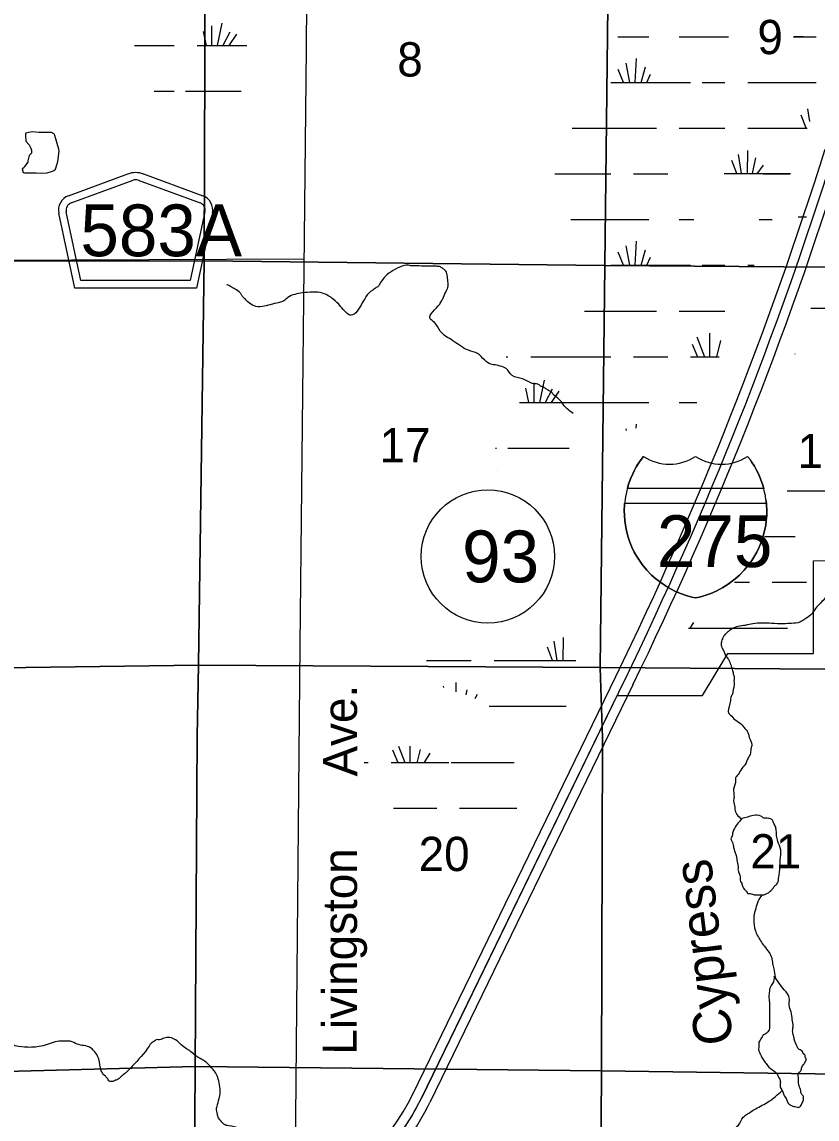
# Model space of a CAD drawing. Extents: x 380424 to 701066, y 1117407 to 1412949.
# Drawn here: x 513753 to 524199, y 1373482 to 1387886 of the extents above; entities that cross this region are included whole.
import ezdxf

# ---------------------------------------------------------------- set-up
doc = ezdxf.new("R2010")
doc.units = 0
for name, color, linetype in [('Cities Incorporated Area', 7, 'Continuous'), ('County Routes Highway Center Lines', 7, 'Continuous'), ('Interstate Divided Highway Outline and Fill', 7, 'Continuous'), ('Interstate Highway Center Lines', 7, 'Continuous'), ('Lakes and Ponds', 7, 'Continuous'), ('Local Roads Paved', 7, 'Continuous'), ('Local Roads Related Text', 7, 'Continuous'), ('Narrow River Creek and Branch and Slough', 7, 'Continuous'), ('Narrow River Creek and Branch and Slough Text', 7, 'Continuous'), ('Roadshields County Roads', 7, 'Continuous'), ('Roadshields Interstates', 7, 'Continuous'), ('Section Lines', 7, 'Continuous'), ('Section Numbers', 7, 'Continuous'), ('Swamps', 7, 'Continuous')]:
    doc.layers.add(name, color=color, linetype=linetype)

msp = doc.modelspace()

# ---------------------------------------------------------------- linework, layer by layer
at = {"layer": 'Cities Incorporated Area'}
msp.add_lwpolyline([(519001, 1373755), (521574, 1379045), (522696, 1379043), (523025, 1379596), (524154, 1379596), (524154, 1380812), (526832, 1380817), (526844, 1382202), (528060, 1382202), (528061, 1383504), (529275, 1383505), (529270, 1384771), (530889, 1384771), (530889, 1385981), (529270, 1385981), (529290, 1387758), (530767, 1387752), (529457, 1389968)], dxfattribs=at)
msp.add_arc((516112, 1375160), 3212, 319.5366, 334.0599, dxfattribs=at)
at = {"layer": 'County Routes Highway Center Lines'}
msp.add_lwpolyline([(517457, 1384773), (507279, 1384726)], dxfattribs=at)
at = {"layer": 'Interstate Divided Highway Outline and Fill'}
for p, q in [((518888, 1373809), (521555, 1379291)), ((521780, 1379182), (519113, 1373700))]:
    msp.add_line(p, q, dxfattribs=at)
for centre, radius, start, end in [((476737, 1401092), 49839, 334.0597, 342.6352), ((476737, 1401092), 50089, 334.0597, 342.6352), ((516112, 1375160), 3087, 295.0995, 334.0599), ((516112, 1375160), 3337, 295.0995, 334.0599)]:
    msp.add_arc(centre, radius, start, end, dxfattribs=at)
at = {"layer": 'Interstate Highway Center Lines'}
msp.add_line((521667, 1379236), (519001, 1373755), dxfattribs=at)
for centre, radius, start, end in [((476737, 1401092), 49964, 334.0597, 342.6352), ((516112, 1375160), 3212, 295.0995, 334.0599)]:
    msp.add_arc(centre, radius, start, end, dxfattribs=at)
at = {"layer": 'Lakes and Ponds'}
msp.add_lwpolyline([(513831, 1386047), (513789, 1385989), (513778, 1385973), (513757, 1385958), (513768, 1385910), (513789, 1385905), (513942, 1385905), (514011, 1385900), (514085, 1385905), (514153, 1385926), (514174, 1385934), (514196, 1385952), (514211, 1386010), (514227, 1386053), (514244, 1386191), (514238, 1386216), (514185, 1386396), (514180, 1386412), (514143, 1386433), (514058, 1386433), (513974, 1386433), (513889, 1386443), (513842, 1386433), (513805, 1386428), (513800, 1386412), (513800, 1386391), (513805, 1386322), (513847, 1386274), (513868, 1386227), (513879, 1386201), (513879, 1386164), (513847, 1386132), (513831, 1386063)], close=True, dxfattribs=at)
for points in [[(523209, 1377426), (523362, 1377466), (523462, 1377460), (523504, 1377434), (523525, 1377434), (523562, 1377429), (523605, 1377413), (523626, 1377376), (523652, 1377323), (523663, 1377270), (523668, 1377202), (523684, 1377128), (523721, 1377017), (523716, 1376885), (523710, 1376784), (523705, 1376716), (523694, 1376642), (523668, 1376563), (523647, 1376547), (523620, 1376510), (523594, 1376483), (523547, 1376446), (523510, 1376431), (523494, 1376425), (523462, 1376425), (523409, 1376425), (523362, 1376431), (523335, 1376441), (523282, 1376452), (523277, 1376462), (523272, 1376473), (523240, 1376499), (523224, 1376531), (523209, 1376579), (523209, 1376584), (523203, 1376589), (523187, 1376658), (523161, 1376748), (523161, 1376800), (523150, 1376858), (523135, 1376943), (523119, 1376990), (523103, 1377049), (523087, 1377112), (523071, 1377175), (523077, 1377181), (523087, 1377223), (523103, 1377276), (523209, 1377426)], [(523636, 1375359), (523768, 1375179), (523837, 1375058), (523832, 1374978), (523858, 1374889), (523874, 1374788), (523885, 1374704), (523879, 1374656), (523885, 1374593), (523895, 1374561), (523906, 1374503), (523916, 1374482), (523964, 1374397), (524011, 1374361), (524017, 1374345), (524038, 1374324), (524043, 1374308), (524043, 1374297), (524054, 1374276), (524048, 1374239), (524022, 1374197), (523995, 1374149), (523990, 1374123), (523958, 1374091), (523953, 1374028), (523958, 1373933), (523980, 1373869), (524001, 1373806), (524022, 1373769), (524017, 1373753), (524022, 1373743), (524017, 1373722), (523995, 1373674), (523964, 1373637), (523943, 1373637), (523906, 1373648), (523895, 1373648), (523863, 1373658), (523821, 1373690), (523805, 1373716), (523784, 1373764), (523779, 1373769), (523763, 1373801), (523742, 1373854), (523716, 1373906), (523716, 1373954), (523710, 1374007), (523694, 1374033), (523673, 1374075), (523636, 1374112), (523547, 1374186), (523510, 1374239), (523473, 1374292), (523457, 1374329), (523441, 1374361), (523430, 1374403), (523436, 1374440), (523436, 1374493), (523451, 1374519), (523488, 1374577), (523515, 1374598), (523541, 1374614), (523573, 1374672), (523573, 1374725), (523573, 1374751), (523573, 1374846), (523573, 1374952), (523573, 1375010), (523568, 1375058), (523568, 1375121), (523573, 1375163), (523594, 1375237), (523615, 1375264), (523636, 1375359)]]:
    msp.add_spline(points, degree=3, dxfattribs=at)
at = {"layer": 'Local Roads Paved'}
msp.add_lwpolyline([(518204, 1395197), (518154, 1394842), (518069, 1394603), (517816, 1394145), (517668, 1393892), (517563, 1393660), (517563, 1393125), (517528, 1392688), (517514, 1391246), (517486, 1387536), (517404, 1379706), (517289, 1367298), (517256, 1362220)], dxfattribs=at)
at = {"layer": 'Narrow River Creek and Branch and Slough'}
for points in [[(518757, 1384686), (518524, 1384542), (518482, 1384489), (518450, 1384442), (518429, 1384410), (518409, 1384399), (518361, 1384363), (518350, 1384357), (518290, 1384302), (518224, 1384197), (518077, 1384035), (517938, 1384152), (517842, 1384248), (517703, 1384324), (517439, 1384329)], [(520995, 1382745), (520878, 1382847), (520840, 1382900), (520789, 1382949), (520741, 1382988), (520716, 1383019), (520679, 1383044), (520637, 1383070), (520601, 1383094), (520564, 1383106), (520547, 1383122), (520478, 1383137), (520330, 1383201), (520193, 1383243), (520116, 1383335), (520080, 1383352), (519987, 1383380), (519913, 1383393), (519833, 1383446), (519739, 1383532), (519619, 1383576), (519414, 1383701), (519248, 1383828), (519173, 1383942), (519117, 1383989), (519242, 1384183), (519256, 1384206), (519270, 1384231), (519281, 1384250), (519320, 1384339), (519342, 1384383), (519342, 1384542), (519322, 1384616), (519286, 1384647), (519253, 1384669), (519198, 1384678), (519156, 1384678), (519098, 1384678), (518973, 1384683), (518929, 1384686), (518904, 1384683), (518876, 1384683), (518848, 1384689), (518757, 1384686)], [(517439, 1384329), (517246, 1384268), (517193, 1384225), (517072, 1384188), (517014, 1384173), (516803, 1384157), (516723, 1384210), (516686, 1384249), (516650, 1384283), (516644, 1384294), (516623, 1384326), (516554, 1384379), (516507, 1384405), (516482, 1384423), (516446, 1384436)], [(526441, 1383988), (526314, 1383306), (526198, 1383069), (526198, 1382979), (526187, 1382916), (526192, 1382831), (526203, 1382731), (526245, 1382594), (526287, 1382472), (526335, 1382319), (526393, 1382203), (526446, 1382050), (526462, 1381881), (526472, 1381780), (526462, 1381669), (526435, 1381611), (526340, 1381500), (526250, 1381374), (526103, 1381247), (525944, 1381036), (525833, 1380925), (525738, 1380861), (525696, 1380803), (525617, 1380708), (525569, 1380587), (525527, 1380529), (525474, 1380492), (525411, 1380460), (525342, 1380423), (525273, 1380407), (525163, 1380402), (525025, 1380434), (524946, 1380471), (524735, 1380523), (524682, 1380518), (524561, 1380523), (524487, 1380486), (524429, 1380444), (524365, 1380397), (524291, 1380307), (524180, 1380185), (524117, 1380101), (524027, 1380038), (523974, 1380006), (523863, 1379990), (523758, 1379985), (523599, 1379990), (523356, 1379985), (523256, 1379964), (523077, 1379916), (523024, 1379874), (522992, 1379847), (522976, 1379826), (522955, 1379789), (522945, 1379758), (522939, 1379705), (522966, 1379641), (522987, 1379589), (523034, 1379515), (523087, 1379372), (523103, 1379314), (523108, 1379293), (523108, 1379245), (523108, 1379214), (523108, 1379171), (523098, 1379124), (523087, 1379066), (523066, 1379018), (523061, 1378976), (523045, 1378897), (523034, 1378855), (523040, 1378807), (523061, 1378786), (523124, 1378723), (523209, 1378664), (523240, 1378622), (523282, 1378575), (523309, 1378490), (523341, 1378400), (523330, 1378342), (523319, 1378268), (523288, 1378210), (523267, 1378158), (523209, 1378084), (523161, 1378004), (523129, 1377957), (523129, 1377930), (523103, 1377814), (523108, 1377714), (523103, 1377656), (523119, 1377577), (523119, 1377550), (523204, 1377419)], [(515847, 1374456), (515772, 1374523), (515620, 1374545), (515562, 1374524), (515509, 1374519), (515498, 1374508), (515472, 1374493), (515445, 1374471), (515424, 1374440), (515202, 1374176), (515113, 1374086), (515060, 1374044), (515018, 1374007), (514981, 1373991), (514933, 1373975), (514896, 1373986), (514880, 1374012), (514849, 1374044), (514801, 1374102), (514785, 1374155), (514748, 1374308), (514695, 1374382), (514653, 1374419), (514479, 1374466), (514389, 1374503), (514326, 1374503), (514241, 1374503), (514030, 1374445), (513829, 1374424), (513666, 1374445), (513507, 1374493), (513349, 1374529), (513185, 1374545), (512953, 1374561), (512736, 1374572), (512525, 1374593), (512440, 1374625), (512372, 1374640), (512361, 1374640), (512298, 1374646), (512271, 1374635), (512208, 1374646), (512161, 1374662), (512081, 1374704), (512029, 1374746), (512002, 1374831), (511891, 1375163), (511865, 1375390), (511854, 1375506), (511865, 1375675), (511881, 1375760), (511891, 1375844), (511897, 1375929), (511891, 1375998), (511881, 1376040), (511833, 1376135), (511801, 1376193), (511733, 1376251), (511706, 1376267), (511622, 1376304), (511559, 1376325), (511395, 1376330), (511337, 1376336), (511279, 1376367), (511231, 1376394), (511210, 1376415), (511168, 1376526), (511147, 1376610), (511126, 1376732), (511115, 1376938), (511099, 1377154), (511046, 1377291), (511004, 1377418), (510957, 1377497), (510930, 1377529), (510909, 1377550), (510856, 1377592), (510851, 1377614), (510851, 1377651), (510830, 1377952)], [(523473, 1376425), (523425, 1376346), (523393, 1376246), (523378, 1376193), (523367, 1376103), (523388, 1375955), (523457, 1375823), (523504, 1375755), (523568, 1375670), (523599, 1375607), (523615, 1375522), (523631, 1375454), (523647, 1375344)], [(517200, 1373250), (516871, 1373294), (516613, 1373362), (516470, 1373394), (516438, 1373399), (516380, 1373442), (516343, 1373484), (516333, 1373500), (516322, 1373542), (516311, 1373626), (516317, 1373648), (516343, 1373753), (516354, 1373790), (516354, 1373906), (516333, 1374007), (516301, 1374086), (516264, 1374133), (516179, 1374223), (516116, 1374265), (516037, 1374313), (515973, 1374366), (515915, 1374403), (515847, 1374456)], [(523589, 1368419), (523557, 1368462), (523541, 1368499), (523494, 1368573), (523478, 1368620), (523462, 1368652), (523451, 1368694), (523451, 1368747), (523446, 1368784), (523462, 1368837), (523494, 1368900), (523520, 1368937), (523552, 1369043), (523562, 1369101), (523568, 1369169), (523552, 1369212), (523531, 1369238), (523520, 1369264), (523499, 1369307), (523467, 1369365), (523362, 1369528), (523309, 1369597), (523288, 1369634), (523261, 1369703), (523235, 1369777), (523219, 1369829), (523214, 1369866), (523198, 1369967), (523193, 1370004), (523209, 1370041), (523145, 1370157), (523140, 1370173), (523108, 1370199), (523066, 1370241), (523003, 1370284), (522944, 1370326), (522876, 1370373), (522834, 1370395), (522786, 1370458), (522754, 1370505), (522739, 1370548), (522733, 1370611), (522733, 1370643), (522733, 1370680), (522712, 1370711), (522675, 1370743), (522649, 1370759), (522622, 1370764), (522580, 1370769), (522527, 1370780), (522469, 1370780), (522416, 1370775), (522406, 1370769), (522342, 1370791), (522316, 1370796), (522295, 1370806), (522263, 1370849), (522263, 1370933), (522263, 1370949), (522279, 1371012), (522284, 1371039), (522305, 1371081), (522358, 1371129), (522443, 1371160), (522511, 1371202), (522548, 1371245), (522622, 1371340), (522665, 1371414), (522686, 1371493), (522717, 1371588), (522765, 1371683), (522797, 1371831), (522786, 1371974), (522812, 1372084), (522839, 1372248), (522849, 1372354), (522855, 1372417), (522860, 1372486), (522881, 1372560), (522886, 1372607), (522876, 1372634), (522865, 1372708), (522855, 1372766), (522860, 1372803), (522923, 1372935), (522966, 1373030), (523040, 1373193), (523103, 1373325), (523124, 1373362), (523177, 1373415), (523209, 1373479), (523230, 1373505), (523272, 1373542), (523330, 1373579), (523393, 1373616), (523562, 1373711), (523741, 1373856)]]:
    msp.add_spline(points, degree=3, dxfattribs=at)
at = {"layer": 'Roadshields County Roads'}
for p, q in [((514364, 1385604), (515144, 1385890)), ((515351, 1385890), (516129, 1385604)), ((514399, 1385510), (515213, 1385809)), ((515282, 1385809), (516094, 1385510)), ((514448, 1384392), (514238, 1385374)), ((514529, 1384492), (514336, 1385395)), ((516158, 1385395), (515964, 1384492)), ((516255, 1385374), (516045, 1384392)), ((516045, 1384392), (514448, 1384392)), ((515964, 1384492), (514529, 1384492))]:
    msp.add_line(p, q, dxfattribs=at)
for centre, radius, start, end in [((515247, 1385608), 300, 69.8264, 110.1725), ((515247, 1385715), 100, 69.8265, 110.1725), ((514433, 1385416), 200, 110.1725, 192.0994), ((516060, 1385416), 200, 347.8996, 69.8265), ((514433, 1385416), 100, 110.1725, 192.0994), ((516060, 1385416), 100, 347.8996, 69.8265)]:
    msp.add_arc(centre, radius, start, end, dxfattribs=at)
at = {"layer": 'Roadshields Interstates'}
for p, q in [((521707, 1381762), (521708, 1381768)), ((523498, 1381762), (521707, 1381762)), ((523534, 1381562), (521671, 1381562)), ((523528, 1381612), (523534, 1381562))]:
    msp.add_line(p, q, dxfattribs=at)
for points in [[(521918, 1382183), (521887, 1382141), (521867, 1382112), (521828, 1382052), (521800, 1382001), (521777, 1381954), (521747, 1381886), (521719, 1381806), (521699, 1381735), (521695, 1381712)], [(521708, 1381768), (521707, 1381762), (521719, 1381806), (521747, 1381886), (521777, 1381954), (521800, 1382001), (521828, 1382052), (521867, 1382112), (521887, 1382141), (521918, 1382183)], [(523510, 1381712), (523506, 1381735), (523486, 1381806), (523458, 1381886), (523428, 1381954), (523405, 1382001), (523377, 1382052), (523338, 1382112), (523318, 1382141), (523287, 1382183)], [(523287, 1382183), (523318, 1382141), (523338, 1382112), (523377, 1382052), (523405, 1382001), (523428, 1381954), (523458, 1381886), (523486, 1381806), (523498, 1381762)], [(521684, 1381662), (521677, 1381612)], [(521695, 1381712), (521685, 1381667), (521684, 1381662)], [(523521, 1381662), (523520, 1381667), (523510, 1381712)], [(523528, 1381612), (523521, 1381662)], [(521677, 1381612), (521674, 1381594), (521670, 1381550), (521667, 1381473), (521668, 1381408), (521673, 1381341), (521681, 1381279), (521696, 1381203), (521718, 1381120), (521740, 1381057), (521767, 1380991), (521798, 1380926), (521823, 1380881), (521865, 1380814), (521901, 1380763), (521962, 1380689), (522025, 1380624), (522082, 1380573), (522176, 1380503), (522245, 1380459), (522330, 1380415), (522403, 1380383), (522492, 1380352), (522552, 1380336), (522603, 1380325)], [(521671, 1381562), (521672, 1381563), (521670, 1381550), (521667, 1381473), (521668, 1381408), (521673, 1381341), (521681, 1381279), (521696, 1381203), (521718, 1381120), (521740, 1381057), (521767, 1380991), (521798, 1380926), (521823, 1380881), (521865, 1380814), (521901, 1380763), (521962, 1380689), (522025, 1380624), (522082, 1380573), (522176, 1380503), (522245, 1380459), (522330, 1380415), (522403, 1380383), (522492, 1380352), (522552, 1380336), (522603, 1380325)], [(522603, 1380325), (522552, 1380336), (522492, 1380352), (522403, 1380383), (522330, 1380415), (522245, 1380459), (522176, 1380503), (522082, 1380573), (522025, 1380624), (521962, 1380689), (521901, 1380763), (521865, 1380814), (521823, 1380881), (521798, 1380926), (521767, 1380991), (521740, 1381057), (521718, 1381120), (521696, 1381203), (521681, 1381279), (521673, 1381341), (521668, 1381408), (521667, 1381473), (521670, 1381550), (521671, 1381562)], [(522603, 1380325), (522653, 1380336), (522713, 1380352), (522802, 1380383), (522875, 1380415), (522960, 1380459), (523029, 1380503), (523123, 1380573), (523180, 1380624), (523243, 1380689), (523304, 1380763), (523340, 1380814), (523382, 1380881), (523407, 1380926), (523438, 1380991), (523466, 1381057), (523487, 1381120), (523509, 1381203), (523524, 1381279), (523532, 1381341), (523537, 1381408), (523538, 1381473), (523535, 1381550), (523531, 1381594), (523528, 1381612)], [(522603, 1380325), (522653, 1380336), (522713, 1380352), (522802, 1380383), (522875, 1380415), (522960, 1380459), (523029, 1380503), (523123, 1380573), (523180, 1380624), (523243, 1380689), (523304, 1380763), (523340, 1380814), (523382, 1380881), (523407, 1380926), (523438, 1380991), (523466, 1381057), (523487, 1381120), (523509, 1381203), (523524, 1381279), (523532, 1381341), (523537, 1381408), (523538, 1381473), (523535, 1381550), (523531, 1381594), (523528, 1381612)], [(523534, 1381562), (523535, 1381550), (523538, 1381473), (523537, 1381408), (523532, 1381341), (523524, 1381279), (523509, 1381203), (523487, 1381120), (523466, 1381057), (523438, 1380991), (523407, 1380926), (523382, 1380881), (523340, 1380814), (523304, 1380763), (523243, 1380689), (523180, 1380624), (523123, 1380573), (523029, 1380503), (522960, 1380459), (522875, 1380415), (522802, 1380383), (522713, 1380352), (522653, 1380336), (522603, 1380325)]]:
    msp.add_lwpolyline(points, dxfattribs=at)
msp.add_circle((519874, 1380869), 875, dxfattribs=at)
for centre, radius, start, end in [((522812, 1381470), 1143, 141.4155, 165.1746), ((522261, 1382698), 619, 236.3685, 303.409), ((522261, 1382698), 619, 236.3685, 303.409), ((522261, 1382698), 619, 236.3685, 303.409), ((522944, 1382703), 623, 236.8281, 303.3923), ((522944, 1382703), 623, 236.8281, 303.3923), ((522944, 1382703), 623, 236.8281, 303.3923)]:
    msp.add_arc(centre, radius, start, end, dxfattribs=at)
at = {"layer": 'Section Lines'}
for points in [[(516166, 1390051), (516147, 1384751), (510484, 1384742), (510477, 1384742), (510408, 1390118), (516156, 1390051)], [(521471, 1389984), (521413, 1384687), (521406, 1384687), (516147, 1384751), (516166, 1390051)], [(526752, 1389920), (526712, 1384648), (526707, 1384648), (521413, 1384687), (521471, 1389984)], [(516147, 1384751), (516074, 1379448), (516074, 1379440), (510560, 1379365), (510479, 1384736), (510477, 1384742), (510484, 1384742)], [(521413, 1384687), (521351, 1379411), (516074, 1379440), (516074, 1379448), (516147, 1384751), (521406, 1384687)], [(526712, 1384648), (526712, 1384642), (526663, 1379370), (521351, 1379411), (521413, 1384687), (526707, 1384648)], [(516074, 1379440), (516056, 1378507), (516030, 1374171), (510557, 1374026), (510558, 1374169), (510562, 1378527), (510560, 1379365)], [(521351, 1379411), (521351, 1379405), (521382, 1378488), (521365, 1374116), (516038, 1374171), (516030, 1374171), (516056, 1378507), (516074, 1379440)], [(526663, 1379370), (526663, 1379363), (526672, 1378473), (526670, 1374041), (521365, 1374116), (521382, 1378488), (521351, 1379405), (521351, 1379411)], [(516030, 1374171), (516030, 1374159), (515992, 1368894), (510634, 1368757), (510631, 1368928), (510557, 1374026)], [(521365, 1374116), (521334, 1368815), (515992, 1368894), (516030, 1374159), (516030, 1374171), (516038, 1374171)], [(526670, 1374041), (526628, 1368762), (526620, 1368762), (521346, 1368815), (521334, 1368815), (521365, 1374116)]]:
    msp.add_lwpolyline(points, close=True, dxfattribs=at)
at = {"layer": 'Swamps'}
for p, q in [((516378, 1387871), (516319, 1387576)), ((516136, 1387762), (516173, 1387576)), ((516245, 1387835), (516245, 1387576)), ((516486, 1387750), (516392, 1387575)), ((516571, 1387726), (516472, 1387577)), ((515454, 1387576), (515754, 1387576)), ((522388, 1387691), (523034, 1387691)), ((523888, 1387691), (524188, 1387691)), ((524018, 1387691), (523888, 1387691)), ((521739, 1387091), (521693, 1387345)), ((521810, 1387091), (521827, 1387407)), ((521887, 1387091), (521945, 1387295)), ((521654, 1387091), (521588, 1387263)), ((521963, 1387091), (522012, 1387199)), ((521488, 1387091), (522538, 1387091)), ((522688, 1387091), (522988, 1387091)), ((523288, 1387091), (523888, 1387091)), ((523888, 1387091), (524188, 1387091)), ((524054, 1386492), (523988, 1386664)), ((522388, 1386491), (522988, 1386491)), ((523288, 1386491), (523888, 1386491)), ((523206, 1385895), (523167, 1386148)), ((523284, 1385895), (523290, 1386199)), ((523144, 1385896), (523078, 1386069)), ((523351, 1385895), (523394, 1386101)), ((523414, 1385894), (523497, 1386008)), ((521788, 1385891), (522238, 1385891)), ((522978, 1385895), (523850, 1385895)), ((523492, 1385891), (523840, 1385891)), ((522388, 1385291), (522579, 1385291)), ((521810, 1384691), (521827, 1385007)), ((521654, 1384691), (521588, 1384863)), ((521739, 1384691), (521693, 1384945)), ((521887, 1384691), (521945, 1384895)), ((521488, 1384691), (522538, 1384691)), ((521963, 1384691), (522012, 1384799)), ((522688, 1384691), (522988, 1384691)), ((522388, 1384091), (522988, 1384091)), ((522618, 1383753), (522721, 1383491)), ((522787, 1383802), (522787, 1383491)), ((522557, 1383657), (522628, 1383491)), ((520438, 1383491), (521488, 1383491)), ((521788, 1383491), (522238, 1383491)), ((520479, 1383149), (520479, 1382891)), ((520612, 1383185), (520553, 1382891)), ((520370, 1383077), (520408, 1382891)), ((520721, 1383065), (520627, 1382890)), ((520805, 1383040), (520706, 1382891)), ((520288, 1382891), (521988, 1382891)), ((523610, 1380529), (524060, 1380529)), ((520863, 1379502), (520868, 1379806)), ((520722, 1379503), (520656, 1379676)), ((520785, 1379502), (520745, 1379755)), ((519957, 1379502), (520557, 1379502)), ((518622, 1378328), (518693, 1378162)), ((519503, 1377562), (519953, 1377562)), ((519953, 1377562), (520253, 1377562))]:
    msp.add_line(p, q, dxfattribs=at)
for points in [[(515231, 1387576), (515454, 1387576)], [(516054, 1387576), (516709, 1387576)], [(521583, 1387691), (521988, 1387691)], [(515489, 1386976), (515754, 1386976)], [(515904, 1386976), (516635, 1386976)], [(524102, 1386581), (524077, 1386744)], [(520981, 1386491), (522088, 1386491)], [(523888, 1386491), (524070, 1386491)], [(520756, 1385891), (521488, 1385891)], [(520965, 1385291), (521988, 1385291)], [(523438, 1385291), (523608, 1385291)], [(523950, 1385329), (524060, 1385329)], [(523288, 1384691), (523374, 1384691)], [(524117, 1384129), (524360, 1384129)], [(521144, 1384091), (522088, 1384091)], [(522932, 1383705), (522878, 1383491)], [(523908, 1383529), (523910, 1383529)], [(520113, 1383491), (520138, 1383491)], [(522538, 1383491), (522912, 1383491)], [(522388, 1382891), (522619, 1382891)], [(521697, 1382521), (521693, 1382545)], [(521824, 1382555), (521827, 1382607)], [(519973, 1382291), (519988, 1382291)], [(520138, 1382291), (520942, 1382291)], [(520000, 1381992), (520000, 1381994)], [(523804, 1381729), (524360, 1381729)], [(523510, 1381129), (523910, 1381129)], [(523113, 1380529), (523310, 1380529)], [(522512, 1379929), (523810, 1379929)], [(522576, 1380001), (522528, 1379929)], [(519070, 1379502), (519656, 1379502)], [(520557, 1379502), (521032, 1379502)], [(519455, 1379213), (519455, 1379093)], [(519286, 1379164), (519292, 1379149)], [(519600, 1379116), (519584, 1379051)], [(519733, 1379056), (519701, 1379000)], [(519890, 1378902), (520557, 1378902)], [(520557, 1378902), (520903, 1378902)], [(518699, 1378380), (518785, 1378162)], [(518851, 1378377), (518851, 1378162)], [(518986, 1378334), (518943, 1378161)], [(519111, 1378285), (519039, 1378162)], [(518251, 1378162), (518303, 1378162)], [(518603, 1378162), (519360, 1378162)], [(519393, 1378162), (519953, 1378162)], [(519953, 1378162), (520220, 1378162)], [(518633, 1377562), (519203, 1377562)]]:
    msp.add_lwpolyline(points, dxfattribs=at)

# ---------------------------------------------------------------- texts
at = {"layer": 'Local Roads Related Text'}
for s, rotation, p in [('Ave.', 90.3169, (518160, 1377980)), ('Livingston', 89.9145, (518152, 1374328))]:
    msp.add_text(s, height=450, rotation=rotation, dxfattribs=at).set_placement(p)
at = {"layer": 'Narrow River Creek and Branch and Slough Text'}
msp.add_text('Cypress', height=500, rotation=96.9693, dxfattribs=at).set_placement((523099, 1374482))
at = {"layer": 'Roadshields County Roads'}
msp.add_text('583A', height=680, rotation=359.9995, dxfattribs=at).set_placement((514521, 1384810))
at = {"layer": 'Roadshields Interstates'}
for s, rotation, p in [('275', 359.9995, (522095, 1380729)), ('93', 359.9992, (519536, 1380529))]:
    msp.add_text(s, height=680, rotation=rotation, dxfattribs=at).set_placement(p)
at = {"layer": 'Section Numbers'}
for s, p in [('9', (523415, 1387463)), ('8', (518684, 1387170)), ('17', (518451, 1382103)), ('16', (523941, 1382028)), ('20', (518965, 1376738)), ('21', (523322, 1376772))]:
    msp.add_text(s, height=450, dxfattribs=at).set_placement(p)

doc.saveas('drawing.dxf')
